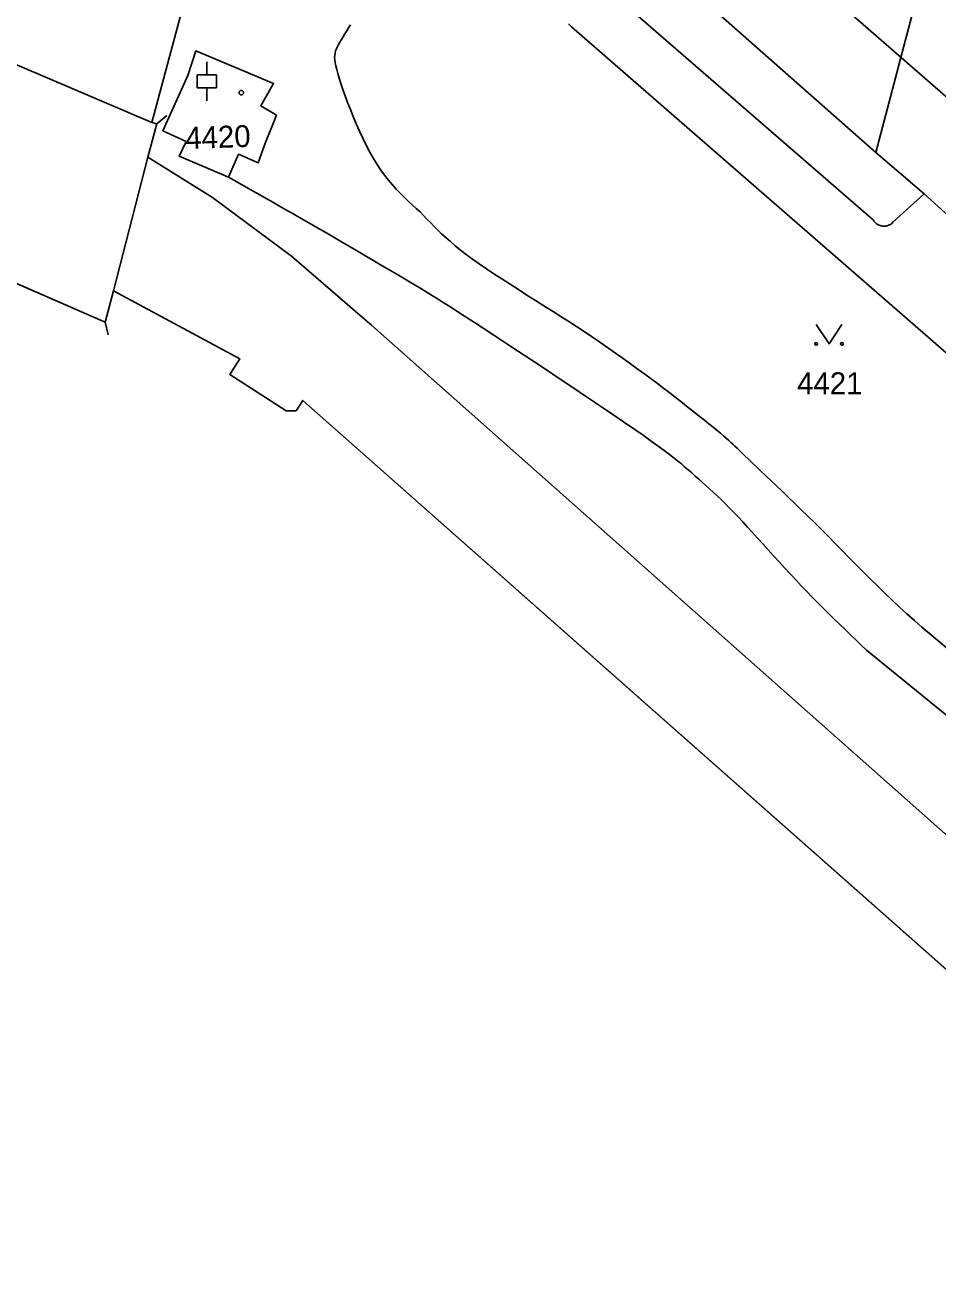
# Model space of a CAD drawing. Extents: x -756746 to -753363, y -1166406 to -1161727.
# Drawn here: x -755799.5 to -755728.8, y -1165864.8 to -1165768 of the extents above; entities that cross this region are included whole.
import ezdxf

# ---------------------------------------------------------------- set-up
doc = ezdxf.new("R2010")
doc.units = 0
for name, color, linetype in [('Hranice kat_území', 7, 'Continuous'), ('Hranice parcel', 7, 'Continuous'), ('Parcelní čísla', 7, 'Continuous'), ('Vnitřní kresba', 7, 'Continuous'), ('Značky budov', 7, 'Continuous'), ('Značky kultur', 7, 'Continuous')]:
    doc.layers.add(name, color=color, linetype=linetype)

msp = doc.modelspace()

# ---------------------------------------------------------------- linework, layer by layer
at = {"layer": 'Hranice kat_území'}
for points in [[(-755918.05, -1165764.1), (-755906.71, -1165761.65), (-755901.64, -1165760.82), (-755901.42, -1165762.23), (-755895.47, -1165761.26), (-755895.64, -1165759.94), (-755879.22, -1165759.17), (-755860.3, -1165762.72), (-755831.83, -1165773.16), (-755820.21, -1165777.17), (-755818.72, -1165777.67), (-755806.32, -1165782.32), (-755807.02, -1165785.03), (-755793.27, -1165791.01), (-755792.63, -1165788.59), (-755782.86, -1165793.86), (-755783.63, -1165795.05)], [(-755783.63, -1165795.05), (-755779.27, -1165797.87), (-755778.5, -1165797.87), (-755777.97, -1165797.06), (-755712.76, -1165854.72), (-755711.13, -1165856.11), (-755691.45, -1165873.93)]]:
    msp.add_lwpolyline(points, dxfattribs=at)
at = {"layer": 'Hranice parcel'}
for p, q in [((-755729.59, -1165762.52), (-755733.65, -1165777.9)), ((-755793.27, -1165791.01), (-755807.02, -1165785.03)), ((-755712.76, -1165854.72), (-755777.97, -1165797.06))]:
    msp.add_line(p, q, dxfattribs=at)
for points in [[(-755789.66, -1165775.57), (-755787.98, -1165769.32), (-755785.33, -1165759.47), (-755784.97, -1165756.94)], [(-755733.65, -1165777.9), (-755750.89, -1165762.66), (-755753.94, -1165759.23)], [(-755803.1, -1165769.84), (-755799.88, -1165771.21), (-755789.66, -1165775.57)], [(-755780.01, -1165775.01), (-755781.24, -1165774.29), (-755780.24, -1165772.55), (-755786.26, -1165770.03), (-755786.88, -1165771.94), (-755788.81, -1165776.21), (-755787.02, -1165777.05), (-755787.55, -1165778.18), (-755783.74, -1165779.79), (-755782.95, -1165778.01), (-755781.43, -1165778.69), (-755780.93, -1165777.24), (-755780.01, -1165775.01)], [(-755789.66, -1165775.57), (-755789.28, -1165775.67), (-755789.97, -1165778.26), (-755784.96, -1165781.38), (-755778.87, -1165785.91), (-755772.65, -1165791.28), (-755707.99, -1165848.57), (-755707.32, -1165849.16), (-755705.75, -1165850.56), (-755704.99, -1165851.24), (-755688.03, -1165866.34), (-755683.52, -1165871.01), (-755663.15, -1165892.58), (-755663.08, -1165892.51), (-755662.84, -1165892.76)], [(-755733.65, -1165777.9), (-755729.91, -1165781.1), (-755726.65, -1165784.02), (-755701.41, -1165806.24), (-755698.45, -1165808.98), (-755680.18, -1165825.1), (-755677.15, -1165827.77), (-755659.91, -1165843.03), (-755642.65, -1165858.23), (-755638.93, -1165861.53)], [(-755777.97, -1165797.06), (-755778.5, -1165797.87), (-755779.27, -1165797.87), (-755783.63, -1165795.05), (-755782.86, -1165793.86), (-755792.63, -1165788.59), (-755793.27, -1165791.01)]]:
    msp.add_lwpolyline(points, dxfattribs=at)
at = {"layer": 'Vnitřní kresba'}
for p, q in [((-755754.24, -1165765.42), (-755733.83, -1165783.13)), ((-755757.2, -1165768.17), (-755706.09, -1165812.61)), ((-755788.502, -1165775.041), (-755789.279, -1165775.67)), ((-755789.97, -1165778.26), (-755792.63, -1165788.59)), ((-755732.31, -1165783.29), (-755729.91, -1165781.1)), ((-755793.046, -1165791.985), (-755793.27, -1165791.011)), ((-755734.35, -1165816.39), (-755704.6, -1165840.67))]:
    msp.add_line(p, q, dxfattribs=at)
for points in [[(-755841.65, -1165713.82), (-755776.03, -1165731.94), (-755617.2, -1165870.13), (-755550.39, -1165868.88), (-755534.18, -1165889.96)], [(-755774.289, -1165768.011), (-755774.44, -1165768.248), (-755774.588, -1165768.481), (-755774.733, -1165768.712), (-755774.87, -1165768.932), (-755774.998, -1165769.142), (-755775.116, -1165769.344), (-755775.22, -1165769.53), (-755775.31, -1165769.702), (-755775.385, -1165769.867), (-755775.444, -1165770.025), (-755775.487, -1165770.185), (-755775.512, -1165770.353), (-755775.52, -1165770.53), (-755775.509, -1165770.725), (-755775.48, -1165770.945), (-755775.431, -1165771.19), (-755775.362, -1165771.468), (-755775.271, -1165771.789), (-755775.16, -1165772.15), (-755775.027, -1165772.558), (-755774.873, -1165773.014), (-755774.7, -1165773.5), (-755774.511, -1165774.015), (-755774.302, -1165774.558), (-755774.081, -1165775.109), (-755773.847, -1165775.668), (-755773.598, -1165776.234), (-755773.342, -1165776.788), (-755773.076, -1165777.329), (-755772.8, -1165777.856), (-755772.52, -1165778.35), (-755772.236, -1165778.812), (-755771.943, -1165779.248), (-755771.65, -1165779.651), (-755771.354, -1165780.029), (-755771.051, -1165780.389), (-755770.748, -1165780.725), (-755770.443, -1165781.043), (-755770.133, -1165781.352), (-755769.825, -1165781.645), (-755769.515, -1165781.93), (-755769.201, -1165782.213), (-755768.89, -1165782.49)], [(-755757.2, -1165768.17), (-755757.426, -1165767.949)], [(-755783.74, -1165779.79), (-755783.265, -1165780.057), (-755782.782, -1165780.329), (-755782.302, -1165780.599), (-755781.817, -1165780.873), (-755781.318, -1165781.155), (-755780.816, -1165781.439), (-755780.304, -1165781.729), (-755779.774, -1165782.031), (-755779.235, -1165782.339), (-755778.681, -1165782.656), (-755778.102, -1165782.989), (-755777.51, -1165783.33), (-755776.898, -1165783.684), (-755776.263, -1165784.052), (-755775.624, -1165784.424), (-755774.98, -1165784.8), (-755774.327, -1165785.181), (-755773.686, -1165785.557), (-755773.054, -1165785.927), (-755772.429, -1165786.294), (-755771.831, -1165786.646), (-755771.258, -1165786.984), (-755770.708, -1165787.309), (-755770.2, -1165787.61), (-755769.729, -1165787.89), (-755769.281, -1165788.157), (-755768.857, -1165788.411), (-755768.44, -1165788.664), (-755768.014, -1165788.926), (-755767.579, -1165789.196), (-755767.118, -1165789.486), (-755766.614, -1165789.806), (-755766.069, -1165790.155), (-755765.465, -1165790.545), (-755764.784, -1165790.988), (-755764.03, -1165791.48), (-755763.19, -1165792.031), (-755762.263, -1165792.64), (-755761.287, -1165793.284), (-755760.267, -1165793.958), (-755759.206, -1165794.662), (-755758.145, -1165795.368), (-755757.087, -1165796.074), (-755756.036, -1165796.779), (-755755.031, -1165797.456), (-755754.076, -1165798.102), (-755753.177, -1165798.715), (-755752.37, -1165799.27), (-755751.656, -1165799.767), (-755751.024, -1165800.213), (-755750.481, -1165800.604), (-755750.01, -1165800.948), (-755749.599, -1165801.256), (-755749.251, -1165801.525), (-755748.95, -1165801.763), (-755748.688, -1165801.979), (-755748.46, -1165802.171), (-755748.257, -1165802.349), (-755748.069, -1165802.518), (-755747.89, -1165802.68)], [(-755768.89, -1165782.49), (-755768.636, -1165782.763), (-755768.375, -1165783.04), (-755768.111, -1165783.317), (-755767.836, -1165783.597), (-755767.544, -1165783.886), (-755767.239, -1165784.177), (-755766.913, -1165784.476), (-755766.56, -1165784.786), (-755766.183, -1165785.104), (-755765.776, -1165785.432), (-755765.329, -1165785.776), (-755764.85, -1165786.13), (-755764.332, -1165786.498), (-755763.771, -1165786.883), (-755763.187, -1165787.275), (-755762.578, -1165787.675), (-755761.941, -1165788.087), (-755761.296, -1165788.499), (-755760.643, -1165788.914), (-755759.977, -1165789.335), (-755759.32, -1165789.749), (-755758.67, -1165790.16), (-755758.023, -1165790.571), (-755757.4, -1165790.97), (-755756.798, -1165791.36), (-755756.209, -1165791.747), (-755755.645, -1165792.123), (-755755.097, -1165792.493), (-755754.556, -1165792.863), (-755754.034, -1165793.225), (-755753.522, -1165793.585), (-755753.012, -1165793.948), (-755752.513, -1165794.307), (-755752.019, -1165794.667), (-755751.522, -1165795.034), (-755751.03, -1165795.4), (-755750.537, -1165795.77), (-755750.04, -1165796.147), (-755749.554, -1165796.518), (-755749.075, -1165796.886), (-755748.603, -1165797.252), (-755748.15, -1165797.605), (-755747.716, -1165797.947), (-755747.298, -1165798.277), (-755746.909, -1165798.587), (-755746.549, -1165798.877), (-755746.215, -1165799.148), (-755745.92, -1165799.39), (-755745.661, -1165799.606), (-755745.431, -1165799.801), (-755745.229, -1165799.975), (-755745.046, -1165800.137), (-755744.874, -1165800.294), (-755744.711, -1165800.445), (-755744.548, -1165800.6), (-755744.378, -1165800.763), (-755744.197, -1165800.938), (-755743.999, -1165801.13), (-755743.773, -1165801.347), (-755743.52, -1165801.59), (-755743.232, -1165801.864), (-755742.905, -1165802.174), (-755742.551, -1165802.508), (-755742.168, -1165802.87), (-755741.754, -1165803.262), (-755741.322, -1165803.673), (-755740.868, -1165804.106), (-755740.391, -1165804.564), (-755739.904, -1165805.034), (-755739.404, -1165805.521), (-755738.888, -1165806.027), (-755738.37, -1165806.54), (-755737.847, -1165807.063), (-755737.313, -1165807.602), (-755736.78, -1165808.141), (-755736.244, -1165808.685), (-755735.696, -1165809.24), (-755735.152, -1165809.79), (-755734.603, -1165810.34), (-755734.045, -1165810.896), (-755733.49, -1165811.441), (-755732.932, -1165811.983), (-755732.364, -1165812.524), (-755731.8, -1165813.05), (-755731.233, -1165813.568), (-755730.653, -1165814.086), (-755730.069, -1165814.597), (-755729.47, -1165815.111), (-755728.846, -1165815.64), (-755728.205, -1165816.174)], [(-755733.83, -1165783.13), (-755733.783, -1165783.2), (-755733.73, -1165783.265), (-755733.672, -1165783.325), (-755733.608, -1165783.381), (-755733.54, -1165783.43), (-755733.468, -1165783.473), (-755733.393, -1165783.51), (-755733.314, -1165783.54), (-755733.234, -1165783.563), (-755733.151, -1165783.579), (-755733.068, -1165783.588), (-755732.984, -1165783.59), (-755732.9, -1165783.584), (-755732.817, -1165783.571), (-755732.735, -1165783.55), (-755732.656, -1165783.523), (-755732.579, -1165783.489), (-755732.505, -1165783.448), (-755732.436, -1165783.401), (-755732.37, -1165783.348), (-755732.31, -1165783.29)], [(-755747.89, -1165802.68), (-755747.62, -1165802.917), (-755747.345, -1165803.158), (-755747.071, -1165803.401), (-755746.794, -1165803.649), (-755746.508, -1165803.908), (-755746.221, -1165804.173), (-755745.926, -1165804.449), (-755745.62, -1165804.741), (-755745.308, -1165805.045), (-755744.985, -1165805.366), (-755744.647, -1165805.71), (-755744.3, -1165806.07), (-755743.94, -1165806.452), (-755743.562, -1165806.858), (-755743.178, -1165807.277), (-755742.784, -1165807.71), (-755742.376, -1165808.161), (-755741.965, -1165808.615), (-755741.549, -1165809.076), (-755741.122, -1165809.547), (-755740.698, -1165810.013), (-755740.271, -1165810.478), (-755739.837, -1165810.945), (-755739.41, -1165811.4), (-755738.984, -1165811.846), (-755738.554, -1165812.289), (-755738.131, -1165812.72), (-755737.71, -1165813.143), (-755737.284, -1165813.565), (-755736.864, -1165813.978), (-755736.446, -1165814.385), (-755736.023, -1165814.793), (-755735.605, -1165815.194), (-755735.188, -1165815.592), (-755734.767, -1165815.994), (-755734.35, -1165816.39)]]:
    msp.add_lwpolyline(points, dxfattribs=at)
at = {"layer": 'Značky budov'}
msp.add_circle((-755782.737, -1165773.259), 0.175, dxfattribs=at)
at = {"layer": 'Značky kultur'}
for p, q in [((-755785.41, -1165771.891), (-755785.41, -1165770.89)), ((-755786.161, -1165771.891), (-755784.659, -1165771.891)), ((-755786.161, -1165772.892), (-755786.161, -1165771.891)), ((-755784.659, -1165772.892), (-755784.659, -1165771.891)), ((-755786.161, -1165772.892), (-755784.659, -1165772.892)), ((-755785.41, -1165773.89), (-755785.41, -1165772.892))]:
    msp.add_line(p, q, dxfattribs=at)
msp.add_lwpolyline([(-755738.26, -1165791.189), (-755737.26, -1165792.69), (-755736.26, -1165791.189)], dxfattribs=at)
for centre in [(-755738.26, -1165792.689), (-755736.26, -1165792.689)]:
    msp.add_circle(centre, 0.1, dxfattribs=at)

# ---------------------------------------------------------------- texts
at = {"layer": 'Parcelní čísla'}
msp.add_text('4420', height=1.7, rotation=2, dxfattribs=at).set_placement((-755787.05, -1165777.629))
msp.add_text('4421', height=1.7, dxfattribs=at).set_placement((-755739.73, -1165796.59))

doc.saveas('drawing.dxf')
